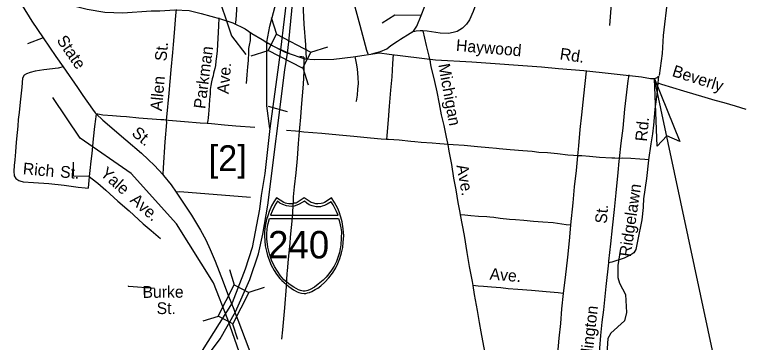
# Model space of a CAD drawing. Extents: x 925297 to 940193, y 663541 to 689899.
# Drawn here: x 928734 to 929667, y 687708 to 688127 of the extents above; entities that cross this region are included whole.
import ezdxf

# ---------------------------------------------------------------- set-up
doc = ezdxf.new("R2010")
doc.units = 0
for name, color, linetype in [('Default', 7, 'Continuous'), ('Exist Horizontal Alignment Tick Large', 7, 'Continuous'), ('Old_Level_28', 7, 'Continuous'), ('Prop Terminator CELL', 7, 'Continuous'), ('Sheet Title CELL', 7, 'Continuous')]:
    doc.layers.add(name, color=color, linetype=linetype)

# ---------------------------------------------------------------- blocks, each defined once
blk = doc.blocks.new('Terminator')
at = {"layer": 'Prop Terminator CELL'}
blk.add_lwpolyline([(-9, 1.55), (0, 0), (-9.05, -1.6), (-7.9, 0)], close=True, dxfattribs=at)

msp = doc.modelspace()

# ---------------------------------------------------------------- linework, layer by layer
at = {"layer": 'Default'}
for p, q in [((929061.65, 688123.11), (929068.51, 688101.54)), ((928770.74, 688097.06), (928750.97, 688089.55)), ((929112.5, 688078.67), (929134.07, 688085.53)), ((929036.3, 688074.11), (929057.87, 688080.97)), ((929102.1, 688058.56), (929108.96, 688036.99)), ((929556.36, 688048.2), (929555.46, 688039.58)), ((929057.82, 688009.8), (929082.25, 688003.25)), ((929008.43, 687801.36), (929014.68, 687781.75)), ((929052.99, 687778.34), (929033.38, 687772.09)), ((928994.33, 687741.54), (928974.72, 687735.29)), ((929012.61, 687732.09), (929018.86, 687712.49))]:
    msp.add_line(p, q, dxfattribs=at)
for points in [[(929954.77, 688606.42), (929947.23, 688598.43), (929915.57, 688562.81), (929863.58, 688508.48), (929842.43, 688488.75), (929834.66, 688480.99), (929804.98, 688446.9), (929760.27, 688396.54), (929716.11, 688347.67), (929651.43, 688277.65), (929637.01, 688263.22), (929592.29, 688213.18), (929577.66, 688195.5), (929570.1, 688171.94), (929567.9, 688147.4), (929562.37, 688100.19), (929560.82, 688077.15), (929557.05, 688048.99), (929557, 688048.94)], [(929056.23, 688091.33), (929060.16, 688111.77), (929071.16, 688153.44), (929077.5, 688199.74), (929086.89, 688301.8)], [(929086.89, 688301.8), (929088.81, 688239.92), (929082.95, 688160.52), (929073.52, 688081.89)], [(929185.46, 688076.32), (929184.09, 688080.79), (929175.51, 688112.79), (929167.96, 688140.71), (929160.42, 688168.06), (929155.83, 688185.87), (929146.33, 688220.36), (929138.93, 688247.28), (929134.13, 688264.91), (929128.59, 688283.93)], [(929253.37, 688125.67), (929258.1, 688137.62), (929267.63, 688164.5), (929279.49, 688198.49), (929291.22, 688230.87), (929311.84, 688288.64)], [(929082.59, 688077.51), (929084.16, 688092.08), (929093.9, 688188.99), (929096.73, 688257.47)], [(929096.73, 688257.47), (929101.82, 688215.02), (929102.38, 688173.71), (929102.38, 688141.45), (929103.51, 688114.29), (929105.78, 688088.26), (929106.34, 688070.15)], [(929016.43, 688114.05), (929017.33, 688120.02), (929019.04, 688146.27), (929020.05, 688167.74), (929020.63, 688181.27)], [(929340.95, 688174.92), (929336.11, 688168.77), (929332.79, 688163.51), (929329.5, 688157.08), (929326.13, 688148.56), (929319.77, 688130.74), (929314.9, 688120.18), (929311.09, 688114.57), (929306.01, 688109.43), (929299.17, 688105.29), (929294.06, 688103.67), (929288.22, 688102.67), (929277.51, 688103.14), (929260.9, 688105.64), (929255.44, 688105.95)], [(928991.04, 688159.4), (929011.34, 688099.72), (929029.63, 688075.6)], [(928735.17, 688153.15), (928756.36, 688118.27), (928770.74, 688097.06)], [(929496, 688154.52), (929496.7, 688151.76), (929493.69, 688112.91)], [(928940.46, 688133.27), (928939.85, 688125.68), (928937.93, 688103.26), (928936.69, 688088.34), (928935.85, 688078.14), (928933.55, 688056.14), (928931.36, 688026.41), (928928.28, 687996), (928927.96, 687991.82)], [(928994.81, 688122.53), (928994.61, 688112.34), (928992.74, 688080.26), (928992.09, 688073.41), (928991.14, 688067.17), (928990.6, 688061.7), (928989.72, 688057.95), (928988.41, 688051.97), (928987.58, 688048.49), (928986.68, 688044.9), (928985.63, 688040.86), (928984.81, 688036.01), (928984.12, 688030.91), (928983.76, 688024.98), (928983.21, 688018.15), (928982.5, 688010.5), (928982.13, 688004.77), (928981.74, 687999.56), (928981.26, 687995.13), (928980.88, 687991.75), (928980.25, 687987.62)], [(929253.37, 688125.67), (929219.48, 688126.14), (929203.36, 688115.66)], [(929241.57, 688104.35), (929243.31, 688105.47), (929247.92, 688111.94), (929253.37, 688125.67)], [(929030.38, 688038.8), (929031.06, 688049.76), (929031.87, 688060.18), (929032.73, 688068.32), (929033.2, 688078.25), (929033.36, 688083.59), (929034.05, 688087.69), (929035.41, 688093.47), (929035.53, 688103.42)], [(929190.19, 688076.58), (929201.44, 688079.74), (929209.26, 688083.08), (929214.66, 688087.18), (929222.94, 688092.72), (929227.04, 688095.46), (929239.24, 688102.85), (929241.57, 688104.35)], [(929255.44, 688105.95), (929252.16, 688106.13), (929246.71, 688105.75), (929241.57, 688104.35)], [(929255.44, 688105.95), (929259.81, 688087.16), (929263.19, 688073.82), (929263.68, 688071.37)], [(928770.74, 688097.06), (928786.95, 688073.18), (928796.19, 688059.95)], [(929056.09, 688091.26), (929054.57, 688092.15), (929051.81, 688093.79)], [(929085.07, 688077.15), (929080.9, 688078.84), (929080.13, 688079.17), (929072.56, 688082.39), (929072.47, 688082.42), (929071.93, 688082.65), (929065.99, 688085.47), (929056.09, 688091.26)], [(929056.23, 688039.43), (929056.23, 688056.73), (929056.23, 688071.67), (929056.23, 688091.33)], [(928935.41, 687608.11), (928944.13, 687631.42), (928952.01, 687647.02), (928961.07, 687662.79), (928970.8, 687677.89), (928996.51, 687713.08), (929016.32, 687747.52), (929034.57, 687788.73), (929045.53, 687821.6), (929051.26, 687846.65), (929057.52, 687883.69), (929079.26, 688056.16), (929082.59, 688077.51)], [(929073.52, 688081.89), (929071.28, 688062.79), (929060.16, 687981.25), (929053.87, 687923.87), (929049.18, 687895.69), (929047.09, 687878.48), (929037.7, 687829.43), (929028.73, 687801.97), (929012.15, 687758.99)], [(929073.52, 688081.89), (929078.06, 688079.77), (929082.59, 688077.51)], [(929217.67, 688075.82), (929216.76, 688064.27), (929215.92, 688047.26), (929214.05, 688030.47), (929212.51, 688009.91), (929211.23, 687992.24), (929209.64, 687972.39), (929209.04, 687967.36)], [(929103.63, 688072.21), (929103.65, 688067.63), (929103.7, 688054.67), (929102.5, 688037.73), (929100.15, 688008.18), (929099.11, 687995.65), (929098.12, 687982.31), (929097.7, 687977.37)], [(929103.63, 688072.21), (929098.53, 688073.13)], [(929168.62, 688073.34), (929170.48, 688064.6), (929171.57, 688057.45), (929172.34, 688046.25), (929172.81, 688038.93), (929172.19, 688031.62), (929171.41, 688023.69), (929170.17, 688016.07), (929170.01, 688015.91)], [(929263.68, 688071.37), (929264.61, 688066.72), (929264.96, 688065.1), (929265.82, 688060.39), (929270.24, 688041.44), (929273.37, 688028.18), (929276.11, 688012.93), (929279.02, 687998.88), (929282.15, 687984.99), (929285.36, 687970.2), (929287.07, 687962.66), (929287.31, 687961)], [(928796.19, 688059.95), (928789.8, 688058.52), (928771.6, 688056.34), (928760.59, 688054.51), (928754.37, 688052.94), (928749.47, 688051.22), (928746.42, 688049.25), (928744.53, 688045.37), (928743.33, 688034.1), (928741.47, 688014.91), (928740.15, 688001.75), (928738.99, 687992.68), (928738.31, 687984.52), (928737.4, 687976.21), (928736.32, 687963.78), (928735.28, 687951.46), (928734.6, 687941.41), (928733.67, 687934.06), (928733.22, 687926.81), (928733.69, 687920.8), (928735.67, 687917.63), (928739.63, 687914.86), (928741.01, 687914.47)], [(928796.19, 688059.95), (928814.45, 688033.81), (928821.57, 688023.61), (928833.81, 688005.87), (928837.36, 688001.16), (928838.24, 688000.2)], [(929463.76, 688054.67), (929460.45, 688023.1), (929458.15, 687998.78), (929456.03, 687980.04), (929454.08, 687959.24), (929452.99, 687946.68)], [(929518.47, 688049.83), (929516.92, 688042.25), (929513.04, 688006.07), (929510.67, 687981.9), (929508.3, 687962.63), (929505.95, 687943.23)], [(929060.16, 687981.25), (929056.23, 688010.34), (929056.23, 688028.42), (929056.23, 688039.43)], [(929555.46, 688039.58), (929554.88, 688034.05), (929554.01, 688024.64), (929551.67, 688006.02), (929550.2, 687990.36), (929549.65, 687985.44)], [(929555.46, 688039.58), (929559.89, 688037.77), (929588.04, 688029.5), (929615.48, 688021.33), (929628.28, 688017.64), (929639.8, 688014.33), (929654.12, 688010.15), (929667.92, 688005.98)], [(929515.99, 687400.3), (929510.05, 687409.18), (929476.16, 687440.71), (929427.11, 687468.59), (929377.69, 687485.99), (929210.74, 687526.74), (929074.44, 687586.56), (929047.31, 687621.23), (929006.44, 687737.57), (928988.15, 687784.53), (928940.79, 687859.64), (928883.04, 687923.8), (928817.96, 687969.07), (928783.14, 688020.96)], [(928838.24, 688000.2), (928837.47, 687993.4), (928836.3, 687983.82), (928834.75, 687968.3), (928832.74, 687949.35), (928831.66, 687939.67), (928830.41, 687927.81), (928829.56, 687920.06)], [(928927.96, 687991.82), (928924.96, 687992.23), (928920.84, 687992.42), (928892.87, 687994.7), (928877.3, 687996.07), (928869.51, 687996.77), (928859.08, 687997.44), (928846.88, 687998.4), (928838.24, 688000.2)], [(928838.24, 688000.2), (928846.89, 687991.89), (928876.43, 687967.05), (928896.19, 687949.72), (928904.86, 687941.94), (928913, 687934.03), (928923.4, 687922.48)], [(928927.96, 687991.82), (928928.05, 687988.95), (928926.13, 687964.5), (928923.76, 687931), (928923.4, 687922.48)], [(928980.25, 687987.62), (928971.31, 687988.14), (928951.12, 687989.67), (928930.88, 687991.43), (928927.96, 687991.82)], [(929041.17, 687982.5), (929016.86, 687984.44), (929002.2, 687985.52), (928985.61, 687987.32), (928980.25, 687987.62)], [(929549.65, 687985.44), (929548.44, 687974.73), (929546.53, 687961.99), (929543.68, 687941.41)], [(929097.7, 687977.37), (929092.74, 687977.87), (929081.27, 687978.85)], [(929097.7, 687977.37), (929096.43, 687962.39), (929094.79, 687942.92), (929093.23, 687924.87), (929091.09, 687906.73), (929089.92, 687894.17), (929089.71, 687889.72)], [(929209.04, 687967.36), (929202.05, 687967.86), (929197.49, 687968.31), (929184.38, 687969.6), (929167.33, 687971.28), (929148.73, 687973.04), (929126.45, 687974.84), (929103.54, 687976.79), (929097.7, 687977.37)], [(929245.4, 687964.31), (929240.3, 687964.78), (929225.01, 687966.41), (929211.61, 687967.18), (929209.04, 687967.36)], [(929287.31, 687961), (929282.57, 687961.38), (929277.31, 687961.94), (929267.33, 687962.75), (929253.39, 687963.58), (929245.4, 687964.31)], [(929349.31, 687955.92), (929339.75, 687956.86), (929324.99, 687958.09), (929308.08, 687959.54), (929294.29, 687960.44), (929287.31, 687961)], [(929287.31, 687961), (929288.57, 687952.29), (929291.88, 687935.31), (929294.62, 687917.91), (929297.36, 687903.12), (929300.3, 687886.94), (929302.5, 687874.37), (929303.09, 687871.19)], [(929452.99, 687946.68), (929447.88, 687947.05), (929440.66, 687947.49), (929427.19, 687948.93), (929414.58, 687950.23), (929403.51, 687950.89), (929394.91, 687951.87), (929383.03, 687953.06), (929366.68, 687954.3), (929352.82, 687955.58), (929349.31, 687955.92)], [(929452.99, 687946.68), (929452.58, 687941.97), (929451.09, 687927.63), (929448.66, 687907.05), (929446.97, 687886.38), (929443.79, 687858.56), (929443.74, 687857.91)], [(929505.95, 687943.23), (929500.52, 687943.33), (929496.71, 687943.48), (929480.88, 687944.27), (929468.35, 687945.67), (929458.43, 687946.29), (929452.99, 687946.68)], [(928829.56, 687920.06), (928809.32, 687920.73), (928809.59, 687938.46)], [(929505.95, 687943.23), (929505.51, 687939.6), (929504.18, 687925.12), (929501.67, 687899.33), (929499.5, 687878.07), (929497.16, 687854.8), (929494.94, 687834.38), (929492.45, 687812.18), (929492.2, 687809.9)], [(929543.68, 687941.41), (929538.77, 687941.68), (929532.26, 687942.3), (929520.73, 687943.18), (929510.13, 687943.3), (929505.95, 687943.23)], [(929543.68, 687941.41), (929543.62, 687941), (929540.76, 687917.71), (929537.25, 687891.63), (929536.66, 687881.78), (929536.55, 687880.72)], [(928829.56, 687920.06), (928829, 687914.97), (928828.33, 687905.67), (928828.27, 687905.14)], [(928829.56, 687920.06), (928833.21, 687917.32), (928840.42, 687911.53), (928850.79, 687902.51), (928866.24, 687888.71), (928880.38, 687876.36), (928898.44, 687859.8), (928908.65, 687851.17), (928920.72, 687841.17)], [(928923.4, 687922.48), (928924.49, 687921.27), (928934.02, 687909.6), (928940.56, 687900.07)], [(928741.01, 687914.47), (928745.28, 687913.29), (928758.39, 687912.38), (928778.2, 687911.22), (928797.37, 687908.86), (928815.27, 687906.65), (928824.58, 687905.44), (928828.27, 687905.14)], [(929035.3, 687893.31), (928945.15, 687900.47), (928940.56, 687900.07)], [(928940.56, 687900.07), (928944.16, 687894.82), (928960.16, 687870.65), (928971.7, 687851.57), (928978.24, 687839.11), (928984.02, 687826.89), (928990.49, 687812.02), (929000.53, 687785.56), (929007.48, 687767.51), (929010.36, 687760.14), (929013.98, 687750.84), (929016.04, 687745.57), (929017.66, 687741.42), (929017.72, 687741.42), (929019.35, 687737.37), (929033.48, 687700.41), (929039.18, 687685.94), (929042.14, 687678.67)], [(929089.71, 687889.72), (929088.64, 687867.33), (929086.24, 687842.65), (929085.54, 687835.21), (929083.56, 687814.45), (929082.31, 687799.88)], [(929536.55, 687880.72), (929534.97, 687864.86), (929529.53, 687837.51), (929527.13, 687826.79), (929524.81, 687822.8), (929521.03, 687819.94), (929512.52, 687816.07), (929496.67, 687810.91), (929492.2, 687809.9)], [(929340.89, 687868.19), (929337.1, 687868.59), (929326.52, 687869.16), (929316.79, 687870.1), (929308.87, 687870.71), (929303.09, 687871.19)], [(929303.09, 687871.19), (929305.48, 687858.2), (929307.98, 687844.61), (929311.52, 687823.05), (929314.67, 687805.22), (929318.21, 687786.09), (929319.15, 687780.81)], [(929443.74, 687857.91), (929438.56, 687858.3), (929421.78, 687861.12), (929408.61, 687861.69), (929396.76, 687862.74), (929384.32, 687863.79), (929373.91, 687864.65), (929365.86, 687865.32), (929354.03, 687866.66), (929345.97, 687867.65), (929340.89, 687868.19)], [(929443.74, 687857.91), (929442.06, 687837.82), (929439.88, 687817.1), (929436.98, 687791.33), (929434.48, 687771.13), (929434.45, 687770.84)], [(929507.8, 687828.4), (929504.21, 687806.51), (929504.47, 687791.28), (929506.61, 687783.99), (929514.07, 687769.33), (929515.26, 687746.47), (929512.88, 687735.75), (929495.51, 687720.36), (929491.66, 687713.29), (929485.9, 687630.65), (929476.55, 687604.15), (929462.13, 687581.45), (929454.5, 687536.51), (929452.27, 687496.15), (929444.46, 687462.49)], [(929492.2, 687809.9), (929489, 687779.92), (929485.99, 687750.03), (929484.02, 687734.22), (929482.22, 687717.17), (929480.91, 687701.02), (929478.68, 687678.32), (929476.53, 687658.97), (929473.72, 687633.72), (929472.82, 687620.76), (929470.1, 687603.84), (929468.4, 687592.95), (929467.52, 687579.49), (929465.53, 687555.26), (929462.66, 687528.82), (929459.65, 687493.79), (929460.05, 687485.11)], [(929082.31, 687799.88), (929082.01, 687796.39), (929080.88, 687779.72), (929078.89, 687752.54), (929076.11, 687724.4), (929075.2, 687712.49)], [(928879.11, 687780.41), (928879.47, 687780.37), (928880.08, 687780.33), (928912.73, 687777.69)], [(929434.45, 687770.84), (929427.98, 687771.47), (929412.94, 687772.86), (929394.04, 687774.52), (929376.5, 687776.03), (929364.38, 687776.78), (929355.12, 687777.91), (929343.02, 687778.93), (929332.76, 687779.6), (929326.1, 687780.13), (929319.15, 687780.81)], [(929319.15, 687780.81), (929321.15, 687769.56), (929324.76, 687748.93), (929327.16, 687733.62), (929329.54, 687722.08), (929335.45, 687689.99)], [(929434.45, 687770.84), (929432.54, 687751.29), (929430.99, 687732.58), (929429.17, 687713.72), (929427.47, 687694.22), (929426.35, 687683.79)], [(929012.15, 687758.99), (928957.05, 687671.52), (928942.28, 687645.25), (928924.5, 687609.11), (928919.86, 687595.69), (928913.08, 687574.82), (928892.74, 687479.86), (928882.83, 687438.12), (928873.45, 687414.64), (928866.64, 687400.3)]]:
    msp.add_lwpolyline(points, dxfattribs=at)
for points in [[(929068.51, 688101.54), (929112.55, 688078.77), (929101.91, 688058.2), (929057.87, 688080.97)], [(929103.96, 687770.79), (929105.85, 687770.97), (929108.4, 687771.47), (929110.88, 687772.28), (929113.7, 687773.53), (929117.86, 687775.84), (929121.21, 687777.8), (929125.08, 687780.4), (929130.31, 687785.14), (929135.52, 687790.63), (929140.11, 687796.84), (929143.76, 687802.64), (929146.98, 687809.27), (929149.67, 687815.45), (929151.8, 687822.52), (929153.21, 687829.37), (929153.93, 687836.5), (929154.4, 687844.42), (929153.86, 687853.33), (929152.32, 687862.44), (929150.86, 687868.11), (929148.65, 687874.9), (929146.86, 687879.23), (929142.69, 687886.92), (929138.94, 687892.84), (929133.49, 687889.01), (929129.94, 687887.12), (929127.77, 687886.14), (929125.54, 687885.71), (929121.44, 687885.21), (929118.86, 687885.33), (929116.48, 687885.87), (929114.45, 687886.31), (929112.8, 687887.12), (929103.96, 687892.84), (929095.1, 687887.12), (929093.24, 687886.27), (929091.34, 687885.87), (929089.51, 687885.36), (929086.48, 687885.21), (929084.17, 687885.28), (929081.8, 687885.71), (929079.92, 687886.1), (929077.82, 687887.12), (929068.8, 687892.84), (929065.25, 687887.7), (929062.36, 687882.61), (929059.29, 687875.43), (929057.38, 687869.86), (929056.02, 687865.29), (929054.34, 687856.9), (929053.48, 687849.59), (929053.33, 687844.42), (929054.28, 687831.52), (929055.69, 687824.64), (929057.13, 687819.09), (929061.91, 687807.08), (929065.5, 687800.35), (929068.58, 687795.52), (929072.89, 687790.09), (929075.23, 687787.5), (929084.19, 687779.66), (929090.18, 687775.57), (929094.96, 687772.99), (929097.21, 687772.14), (929100.72, 687771.16)], [(929069.87, 687888.69), (929067.67, 687885.31), (929065.14, 687880.74), (929063.11, 687876), (929061.04, 687870.77), (929147.35, 687870.74), (929145.34, 687875.23), (929143.19, 687879.73), (929140.94, 687883.84), (929138.19, 687887.82), (929133.35, 687884.77), (929129.83, 687883.11), (929126.99, 687882.13), (929124.59, 687881.59), (929120.88, 687881.3), (929119.21, 687881.4), (929114.03, 687882.57), (929110.52, 687884), (929107.18, 687886.23), (929104.47, 687888.78), (929097.63, 687884.64), (929094.6, 687883.31), (929091.11, 687882.41), (929087.29, 687881.94), (929081.41, 687882.57), (929076.79, 687884.16), (929072.82, 687886.23)], [(929147.86, 687866.48), (929148.78, 687864.04), (929150.06, 687858.63), (929150.72, 687854.47), (929151.41, 687849.67), (929151.17, 687841.44), (929150.77, 687832.93), (929149.99, 687827.88), (929148.94, 687823.3), (929147.51, 687818.2), (929145.2, 687811.44), (929142.02, 687805.71), (929138.05, 687799.34), (929133.75, 687793.77), (929131.88, 687791.46), (929128.34, 687787.72), (929121.9, 687782.55), (929117.2, 687779.03), (929111.56, 687775.71), (929108.7, 687774.43), (929105.37, 687773.73), (929102.63, 687773.93), (929099.3, 687774.81), (929096.61, 687775.55), (929090.72, 687778.73), (929085.95, 687781.91), (929078, 687788.44), (929073.71, 687793.46), (929069.7, 687799.34), (929066.13, 687805.36), (929062.31, 687813.29), (929059.62, 687821.27), (929057.66, 687829.89), (929056.34, 687840.42), (929056.19, 687846.83), (929056.58, 687853), (929057.17, 687856.23), (929057.95, 687860.24), (929059.53, 687866.44)], [(929033.38, 687772.09), (929012.69, 687732.05), (928993.99, 687741.71), (929014.68, 687781.75)]]:
    msp.add_lwpolyline(points, close=True, dxfattribs=at)
at = {"layer": 'Exist Horizontal Alignment Tick Large'}
msp.add_line((929650.34, 687580.22), (929551.29, 688044.55), dxfattribs=at)
at = {"layer": 'Old_Level_28'}
for points in [[(928639.49, 688117.35), (928654.87, 688130.19), (928667.72, 688136.23), (928688.3, 688144.9), (928703.27, 688148.91), (928717.66, 688152.47), (928725.18, 688152.94), (928736.48, 688153.09), (928770.68, 688148.21), (928827.03, 688133.76), (928849.33, 688129.77), (928872.49, 688128.91), (928908.64, 688131.6), (928919.8, 688131.64), (928939.04, 688132.57), (928957.06, 688131.75), (928972.56, 688128.16), (928997.1, 688121.24), (929012.71, 688116.14), (929028.65, 688108.55), (929037.28, 688102.7), (929050.12, 688094.96), (929057.7, 688090.16), (929073.52, 688081.89)], [(929073.52, 688081.89), (929078.06, 688079.77), (929082.59, 688077.51)], [(929555.76, 688047.7), (929554.17, 688046.11), (929551.29, 688044.55), (929545.82, 688044.77), (929534.51, 688046.77), (929461.05, 688054.99), (929428.8, 688057.64), (929406.87, 688059.42), (929317.81, 688066.08), (929271.68, 688068.74), (929212.27, 688075.78), (929200.26, 688077.33), (929166.53, 688072.29), (929141.72, 688069.19), (929116.91, 688068.8), (929105.28, 688069.96), (929082.59, 688077.51)]]:
    msp.add_lwpolyline(points, dxfattribs=at)

# ---------------------------------------------------------------- block references
at = {"layer": 'Sheet Title CELL', "xscale": 9.375000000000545, "yscale": 9.375000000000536, "rotation": 102.04183522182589}
msp.add_blockref('Terminator', (929551.29, 688044.55), dxfattribs=at)

# ---------------------------------------------------------------- texts
at = {"layer": 'Default'}
for s, rotation, p in [('State', 304.72859, (928787.35, 688093.88)), ('Haywood', 355.23978, (929297.35, 688080.36)), ('St.', 85.20566, (928928.14, 688066.82)), ('Parkman', 82.79299, (928977.66, 688005.83)), ('Rd.', 351.5697, (929429.55, 688069.61)), ('Ave.', 85.20566, (929007.49, 688025.01)), ('Michigan', 280.34625, (929274.98, 688062.83)), ('Beverly', 342.29087, (929572.57, 688048.48)), ('Allen', 84.81824, (928922.21, 688003.25)), ('Rd.', 84.42013, (929541.35, 687964.31)), ('St.', 319.93009, (928882.67, 687973.72)), ('Rich', 355.00875, (928744.41, 687922.97)), ('St.', 355.00875, (928791.92, 687919.05)), ('Yale', 318.54993, (928842.61, 687922.39)), ('Ave.', 280.53236, (929298.19, 687934.11)), ('Ridgelawn', 81.70881, (929520.73, 687816.98)), ('Ave.', 318.54993, (928880.67, 687888.54)), ('St.', 85.09078, (929490.05, 687859.46)), ('Ave.', 355.36903, (929340.28, 687788.57)), ('Burke', 0.19702, (928897.64, 687765.25)), ('St.', 359.97396, (928915.63, 687744.55)), ('Wellington', 83.59886, (929468.65, 687661.38))]:
    msp.add_text(s, height=15, rotation=rotation, dxfattribs=at).set_placement(p)
for s, height, p in [('[2]', 32.808, (928981.93, 687927.11)), ('240', 35, (929057.83, 687815.55))]:
    msp.add_text(s, height=height, dxfattribs=at).set_placement(p)

doc.saveas('drawing.dxf')
